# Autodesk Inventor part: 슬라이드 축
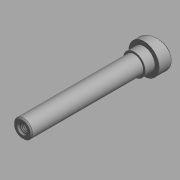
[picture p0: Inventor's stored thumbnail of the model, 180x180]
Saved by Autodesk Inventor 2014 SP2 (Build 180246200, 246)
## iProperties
Created: 2015-11
Part Number: 슬라이드 축
Document SubType Name: 모델링
Designer: mdu
Mass: 174.309 g
Surface Area: 67.5859 cm^2
Volume: 21.5729 cm^3
Density: 8.08 g/cm^3
Material: 스테인리스강
Appearance: 기본값
변환 표준: STEP AP214IS
파일 이름: C:\Users\SeoGD\Desktop\?쒗뿕\異?stp
전처리기: Build: 253, Release: 2010 SP1 - Date: Wed 07/29/2009
전송 단위: 밀리미터
불확실성: 0.01
Author: mdu
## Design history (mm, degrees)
sketch "스케치1"
  geometry: L1 (0, 100)-(7.5, 100); L2 (7.5, 100)-(7.5, 0); L3 (7.5, 0)-(12.5, 0); L4 (12.5, 0)-(12.5, -17); L5 (12.5, -17)-(0, -17); L6 (0, -17)-(0, 100); 1 further point
  constraints: 12 end point, 2 parallel, 2 point on line, 1 perpendicular, 1 vertical
  dimensions: "d0" = 100 distance from line of L1 point (0, 0); "d1" = 15 diameter of L2 L6; "d2" = 25 diameter of L4 L6; "d3" = 17 distance of L3.end L4.end
revolve "회전1" sketch "스케치1" stored, may be unused: angle "d4" = 90 deg
sketch "스케치2"
  geometry: L1 (12.5, 0)-(12.5, -17) reference; L2 (-12.5, -17)-(12.5, -17) reference; L3 (-12.5, 0)-(-12.5, -17) reference; L4 (12.5, -5)-(-12.5, -11.699); L5 (-12.5, 0)-(12.5, 0) reference; 1 further point
  constraints: 2 end point, 2 point on line
  dimensions: "d5" = 75 deg angle of L1 L4; "d6" = 5 distance from line of L4.start L5
extrude "돌출1" cut sketch "스케치2" stored distance "d7" = 10; taper "d8" = 0 deg
chamfer "모따기1" distance "d9" = 1; stored, may be unused: second distance "d10" = 2, angle "d11" = 45 deg
fillet "모깎기1" dims "d12" = 0.5
hole "구멍1" diameter "d15" = 6.647; stored, may be unused: countersink angle "d19" = 90 deg, drill point angle "d21" = 118 deg; dims "d13" = 10, "d14" = 10, "d16" = 17, "d17" = 4, "d18" = 2, "d20" = 20
chamfer "모따기2" distance "d22" = 1; stored, may be unused: second distance "d23" = 2, angle "d24" = 45 deg
sketch "스케치3"
  geometry: C1 r 9 at (0, 0); 1 further point
  constraints: 1 centre point, 1 coincident
  dimensions: "d25" = 18 diameter of C1
extrude "돌출2" join sketch "스케치3" distance "d26" = 8; taper "d27" = 0 deg
node "솔리드1"
node "솔리드 본체"
node "곡면 본체"
node "솔리드2"
